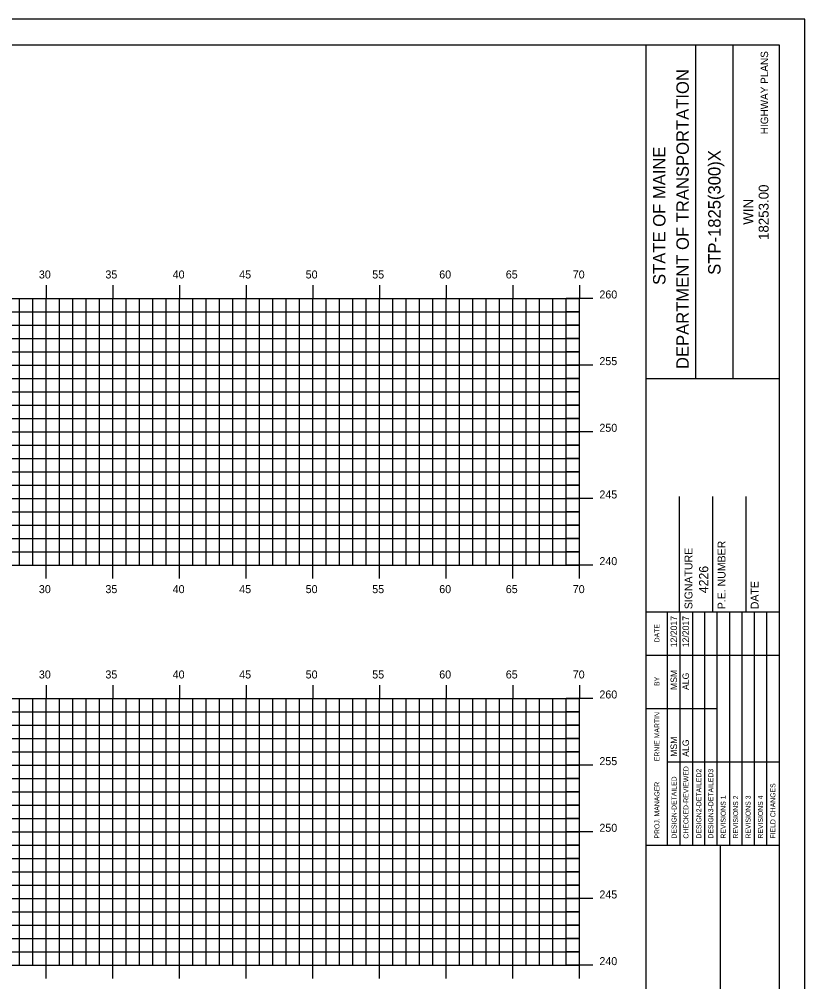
# Model space of a CAD drawing. Extents: x 859575 to 859745, y 366268 to 366378.
# Drawn here: x 859685.8 to 859744.7, y 366306 to 366378.2 of the extents above; entities that cross this region are included whole.
import ezdxf

# ---------------------------------------------------------------- set-up
doc = ezdxf.new("R2010")
doc.units = 0
for name, color, linetype in [('ANNOTATION', 7, 'Continuous'), ('BORDER', 7, 'Continuous'), ('H_V ANNOTATION', 7, 'Continuous'), ('HIGHWAY_TITLE', 7, 'Continuous'), ('MAJOR', 7, 'Continuous'), ('MINOR', 7, 'Continuous'), ('PLOT BOUNDARY', 7, 'Continuous')]:
    doc.layers.add(name, color=color, linetype=linetype)

msp = doc.modelspace()

# ---------------------------------------------------------------- linework, layer by layer
at = {"layer": 'BORDER'}
for p, q in [((859742.797, 366376.236), (859582.797, 366376.236)), ((859732.797, 366271.236), (859732.797, 366376.239)), ((859736.526, 366351.234), (859736.526, 366376.234)), ((859739.321, 366351.234), (859739.321, 366376.234)), ((859742.797, 366271.236), (859742.797, 366376.236)), ((859732.798, 366351.231), (859742.797, 366351.231)), ((859735.297, 366333.739), (859735.297, 366342.387)), ((859737.797, 366333.739), (859737.797, 366342.387)), ((859740.297, 366333.739), (859740.297, 366342.387)), ((859732.797, 366333.739), (859742.797, 366333.739)), ((859732.797, 366316.239), (859742.797, 366316.239)), ((859738.388, 366281.239), (859738.388, 366316.239))]:
    msp.add_line(p, q, dxfattribs=at)
for points in [[(859734.412, 366330.489), (859734.412, 366333.739)], [(859735.345, 366316.242), (859735.345, 366333.739)], [(859736.277, 366333.739), (859736.277, 366316.242)], [(859737.208, 366316.242), (859737.208, 366333.739)], [(859738.14, 366316.242), (859738.14, 366333.739)], [(859739.072, 366316.242), (859739.072, 366333.739)], [(859740.003, 366316.242), (859740.003, 366333.739)], [(859740.935, 366316.242), (859740.935, 366333.739)], [(859741.867, 366316.242), (859741.867, 366333.739)], [(859734.413, 366316.242), (859734.413, 366333.033)], [(859732.797, 366330.489), (859742.797, 366330.489)], [(859732.797, 366326.489), (859734.413, 366326.489)], [(859734.412, 366326.489), (859738.139, 366326.489)], [(859734.412, 366322.489), (859742.797, 366322.489)]]:
    msp.add_lwpolyline(points, dxfattribs=at)
at = {"layer": 'MAJOR'}
for p, q in [((859687.797, 366358.238), (859687.797, 366357.236)), ((859692.797, 366358.238), (859692.797, 366357.236)), ((859697.797, 366358.238), (859697.797, 366357.236)), ((859702.797, 366358.238), (859702.797, 366357.236)), ((859707.797, 366358.238), (859707.797, 366357.236)), ((859712.797, 366358.238), (859712.797, 366357.236)), ((859717.797, 366358.238), (859717.797, 366357.236)), ((859722.797, 366358.238), (859722.797, 366357.236)), ((859727.797, 366358.238), (859727.797, 366357.236)), ((859587.797, 366357.236), (859727.797, 366357.236)), ((859587.797, 366357.236), (859727.797, 366357.236)), ((859587.797, 366357.236), (859727.797, 366357.236)), ((859687.797, 366337.236), (859687.797, 366357.236)), ((859687.797, 366337.236), (859687.797, 366357.236)), ((859692.797, 366337.236), (859692.797, 366357.236)), ((859692.797, 366337.236), (859692.797, 366357.236)), ((859697.797, 366337.236), (859697.797, 366357.236)), ((859697.797, 366337.236), (859697.797, 366357.236)), ((859702.797, 366337.236), (859702.797, 366357.236)), ((859702.797, 366337.236), (859702.797, 366357.236)), ((859707.797, 366337.236), (859707.797, 366357.236)), ((859707.797, 366337.236), (859707.797, 366357.236)), ((859712.797, 366337.236), (859712.797, 366357.236)), ((859712.797, 366337.236), (859712.797, 366357.236)), ((859717.797, 366337.236), (859717.797, 366357.236)), ((859717.797, 366337.236), (859717.797, 366357.236)), ((859722.797, 366337.236), (859722.797, 366357.236)), ((859722.797, 366337.236), (859722.797, 366357.236)), ((859728.799, 366357.236), (859726.795, 366357.236)), ((859727.797, 366337.236), (859727.797, 366357.236)), ((859727.797, 366337.236), (859727.797, 366357.236)), ((859727.797, 366337.236), (859727.797, 366357.236)), ((859587.797, 366352.236), (859727.797, 366352.236)), ((859587.797, 366352.236), (859727.797, 366352.236)), ((859728.799, 366352.236), (859726.795, 366352.236)), ((859587.797, 366347.236), (859727.797, 366347.236)), ((859587.797, 366347.236), (859727.797, 366347.236)), ((859728.799, 366347.236), (859726.795, 366347.236)), ((859587.797, 366342.236), (859727.797, 366342.236)), ((859587.797, 366342.236), (859727.797, 366342.236)), ((859728.799, 366342.236), (859726.795, 366342.236)), ((859587.797, 366337.236), (859727.797, 366337.236)), ((859587.797, 366337.236), (859727.797, 366337.236)), ((859587.797, 366337.236), (859727.797, 366337.236)), ((859687.797, 366336.234), (859687.797, 366337.236)), ((859692.797, 366336.234), (859692.797, 366337.236)), ((859697.797, 366336.234), (859697.797, 366337.236)), ((859702.797, 366336.234), (859702.797, 366337.236)), ((859707.797, 366336.234), (859707.797, 366337.236)), ((859712.797, 366336.234), (859712.797, 366337.236)), ((859717.797, 366336.234), (859717.797, 366337.236)), ((859722.797, 366336.234), (859722.797, 366337.236)), ((859728.799, 366337.236), (859726.795, 366337.236)), ((859727.797, 366336.234), (859727.797, 366337.236)), ((859687.797, 366328.238), (859687.797, 366327.236)), ((859692.797, 366328.238), (859692.797, 366327.236)), ((859697.797, 366328.238), (859697.797, 366327.236)), ((859702.797, 366328.238), (859702.797, 366327.236)), ((859707.797, 366328.238), (859707.797, 366327.236)), ((859712.797, 366328.238), (859712.797, 366327.236)), ((859717.797, 366328.238), (859717.797, 366327.236)), ((859722.797, 366328.238), (859722.797, 366327.236)), ((859727.797, 366328.238), (859727.797, 366327.236)), ((859587.797, 366327.236), (859727.797, 366327.236)), ((859587.797, 366327.236), (859727.797, 366327.236)), ((859687.797, 366307.236), (859687.797, 366327.236)), ((859692.797, 366307.236), (859692.797, 366327.236)), ((859697.797, 366307.236), (859697.797, 366327.236)), ((859702.797, 366307.236), (859702.797, 366327.236)), ((859707.797, 366307.236), (859707.797, 366327.236)), ((859712.797, 366307.236), (859712.797, 366327.236)), ((859717.797, 366307.236), (859717.797, 366327.236)), ((859722.797, 366307.236), (859722.797, 366327.236)), ((859728.799, 366327.236), (859726.795, 366327.236)), ((859727.797, 366307.236), (859727.797, 366327.236)), ((859727.797, 366307.236), (859727.797, 366327.236)), ((859587.797, 366322.236), (859727.797, 366322.236)), ((859728.799, 366322.236), (859726.795, 366322.236)), ((859587.797, 366317.236), (859727.797, 366317.236)), ((859728.799, 366317.236), (859726.795, 366317.236)), ((859587.797, 366312.236), (859727.797, 366312.236)), ((859728.799, 366312.236), (859726.795, 366312.236)), ((859587.797, 366307.236), (859727.797, 366307.236)), ((859587.797, 366307.236), (859727.797, 366307.236)), ((859687.797, 366306.234), (859687.797, 366307.236)), ((859692.797, 366306.234), (859692.797, 366307.236)), ((859697.797, 366306.234), (859697.797, 366307.236)), ((859702.797, 366306.234), (859702.797, 366307.236)), ((859707.797, 366306.234), (859707.797, 366307.236)), ((859712.797, 366306.234), (859712.797, 366307.236)), ((859717.797, 366306.234), (859717.797, 366307.236)), ((859722.797, 366306.234), (859722.797, 366307.236)), ((859728.799, 366307.236), (859726.795, 366307.236)), ((859727.797, 366306.234), (859727.797, 366307.236))]:
    msp.add_line(p, q, dxfattribs=at)
at = {"layer": 'MINOR'}
for p, q in [((859685.797, 366337.236), (859685.797, 366357.236)), ((859685.797, 366337.236), (859685.797, 366357.236)), ((859686.797, 366337.236), (859686.797, 366357.236)), ((859686.797, 366337.236), (859686.797, 366357.236)), ((859688.797, 366337.236), (859688.797, 366357.236)), ((859688.797, 366337.236), (859688.797, 366357.236)), ((859689.797, 366337.236), (859689.797, 366357.236)), ((859689.797, 366337.236), (859689.797, 366357.236)), ((859690.797, 366337.236), (859690.797, 366357.236)), ((859690.797, 366337.236), (859690.797, 366357.236)), ((859691.797, 366337.236), (859691.797, 366357.236)), ((859691.797, 366337.236), (859691.797, 366357.236)), ((859693.797, 366337.236), (859693.797, 366357.236)), ((859693.797, 366337.236), (859693.797, 366357.236)), ((859694.797, 366337.236), (859694.797, 366357.236)), ((859694.797, 366337.236), (859694.797, 366357.236)), ((859695.797, 366337.236), (859695.797, 366357.236)), ((859695.797, 366337.236), (859695.797, 366357.236)), ((859696.797, 366337.236), (859696.797, 366357.236)), ((859696.797, 366337.236), (859696.797, 366357.236)), ((859698.797, 366337.236), (859698.797, 366357.236)), ((859698.797, 366337.236), (859698.797, 366357.236)), ((859699.797, 366337.236), (859699.797, 366357.236)), ((859699.797, 366337.236), (859699.797, 366357.236)), ((859700.797, 366337.236), (859700.797, 366357.236)), ((859700.797, 366337.236), (859700.797, 366357.236)), ((859701.797, 366337.236), (859701.797, 366357.236)), ((859701.797, 366337.236), (859701.797, 366357.236)), ((859703.797, 366337.236), (859703.797, 366357.236)), ((859703.797, 366337.236), (859703.797, 366357.236)), ((859704.797, 366337.236), (859704.797, 366357.236)), ((859704.797, 366337.236), (859704.797, 366357.236)), ((859705.797, 366337.236), (859705.797, 366357.236)), ((859705.797, 366337.236), (859705.797, 366357.236)), ((859706.797, 366337.236), (859706.797, 366357.236)), ((859706.797, 366337.236), (859706.797, 366357.236)), ((859708.797, 366337.236), (859708.797, 366357.236)), ((859708.797, 366337.236), (859708.797, 366357.236)), ((859709.797, 366337.236), (859709.797, 366357.236)), ((859709.797, 366337.236), (859709.797, 366357.236)), ((859710.797, 366337.236), (859710.797, 366357.236)), ((859710.797, 366337.236), (859710.797, 366357.236)), ((859711.797, 366337.236), (859711.797, 366357.236)), ((859711.797, 366337.236), (859711.797, 366357.236)), ((859713.797, 366337.236), (859713.797, 366357.236)), ((859713.797, 366337.236), (859713.797, 366357.236)), ((859714.797, 366337.236), (859714.797, 366357.236)), ((859714.797, 366337.236), (859714.797, 366357.236)), ((859715.797, 366337.236), (859715.797, 366357.236)), ((859715.797, 366337.236), (859715.797, 366357.236)), ((859716.797, 366337.236), (859716.797, 366357.236)), ((859716.797, 366337.236), (859716.797, 366357.236)), ((859718.797, 366337.236), (859718.797, 366357.236)), ((859718.797, 366337.236), (859718.797, 366357.236)), ((859719.797, 366337.236), (859719.797, 366357.236)), ((859719.797, 366337.236), (859719.797, 366357.236)), ((859720.797, 366337.236), (859720.797, 366357.236)), ((859720.797, 366337.236), (859720.797, 366357.236)), ((859721.797, 366337.236), (859721.797, 366357.236)), ((859721.797, 366337.236), (859721.797, 366357.236)), ((859723.797, 366337.236), (859723.797, 366357.236)), ((859723.797, 366337.236), (859723.797, 366357.236)), ((859724.797, 366337.236), (859724.797, 366357.236)), ((859724.797, 366337.236), (859724.797, 366357.236)), ((859725.797, 366337.236), (859725.797, 366357.236)), ((859725.797, 366337.236), (859725.797, 366357.236)), ((859726.797, 366337.236), (859726.797, 366357.236)), ((859726.797, 366337.236), (859726.797, 366357.236)), ((859587.797, 366356.236), (859727.797, 366356.236)), ((859587.797, 366356.236), (859727.797, 366356.236)), ((859727.797, 366356.236), (859726.795, 366356.236)), ((859587.797, 366355.236), (859727.797, 366355.236)), ((859587.797, 366355.236), (859727.797, 366355.236)), ((859727.797, 366355.236), (859726.795, 366355.236)), ((859587.797, 366354.236), (859727.797, 366354.236)), ((859587.797, 366354.236), (859727.797, 366354.236)), ((859727.797, 366354.236), (859726.795, 366354.236)), ((859587.797, 366353.236), (859727.797, 366353.236)), ((859587.797, 366353.236), (859727.797, 366353.236)), ((859727.797, 366353.236), (859726.795, 366353.236)), ((859587.797, 366351.236), (859727.797, 366351.236)), ((859587.797, 366351.236), (859727.797, 366351.236)), ((859727.797, 366351.236), (859726.795, 366351.236)), ((859587.797, 366350.236), (859727.797, 366350.236)), ((859587.797, 366350.236), (859727.797, 366350.236)), ((859727.797, 366350.236), (859726.795, 366350.236)), ((859587.797, 366349.236), (859727.797, 366349.236)), ((859587.797, 366349.236), (859727.797, 366349.236)), ((859727.797, 366349.236), (859726.795, 366349.236)), ((859587.797, 366348.236), (859727.797, 366348.236)), ((859587.797, 366348.236), (859727.797, 366348.236)), ((859727.797, 366348.236), (859726.795, 366348.236)), ((859587.797, 366346.236), (859727.797, 366346.236)), ((859587.797, 366346.236), (859727.797, 366346.236)), ((859727.797, 366346.236), (859726.795, 366346.236)), ((859587.797, 366345.236), (859727.797, 366345.236)), ((859587.797, 366345.236), (859727.797, 366345.236)), ((859727.797, 366345.236), (859726.795, 366345.236)), ((859587.797, 366344.236), (859727.797, 366344.236)), ((859587.797, 366344.236), (859727.797, 366344.236)), ((859727.797, 366344.236), (859726.795, 366344.236)), ((859587.797, 366343.236), (859727.797, 366343.236)), ((859587.797, 366343.236), (859727.797, 366343.236)), ((859727.797, 366343.236), (859726.795, 366343.236)), ((859587.797, 366341.236), (859727.797, 366341.236)), ((859587.797, 366341.236), (859727.797, 366341.236)), ((859727.797, 366341.236), (859726.795, 366341.236)), ((859587.797, 366340.236), (859727.797, 366340.236)), ((859587.797, 366340.236), (859727.797, 366340.236)), ((859727.797, 366340.236), (859726.795, 366340.236)), ((859587.797, 366339.236), (859727.797, 366339.236)), ((859587.797, 366339.236), (859727.797, 366339.236)), ((859727.797, 366339.236), (859726.795, 366339.236)), ((859587.797, 366338.236), (859727.797, 366338.236)), ((859587.797, 366338.236), (859727.797, 366338.236)), ((859727.797, 366338.236), (859726.795, 366338.236)), ((859685.797, 366307.236), (859685.797, 366327.236)), ((859686.797, 366307.236), (859686.797, 366327.236)), ((859688.797, 366307.236), (859688.797, 366327.236)), ((859689.797, 366307.236), (859689.797, 366327.236)), ((859690.797, 366307.236), (859690.797, 366327.236)), ((859691.797, 366307.236), (859691.797, 366327.236)), ((859693.797, 366307.236), (859693.797, 366327.236)), ((859694.797, 366307.236), (859694.797, 366327.236)), ((859695.797, 366307.236), (859695.797, 366327.236)), ((859696.797, 366307.236), (859696.797, 366327.236)), ((859698.797, 366307.236), (859698.797, 366327.236)), ((859699.797, 366307.236), (859699.797, 366327.236)), ((859700.797, 366307.236), (859700.797, 366327.236)), ((859701.797, 366307.236), (859701.797, 366327.236)), ((859703.797, 366307.236), (859703.797, 366327.236)), ((859704.797, 366307.236), (859704.797, 366327.236)), ((859705.797, 366307.236), (859705.797, 366327.236)), ((859706.797, 366307.236), (859706.797, 366327.236)), ((859708.797, 366307.236), (859708.797, 366327.236)), ((859709.797, 366307.236), (859709.797, 366327.236)), ((859710.797, 366307.236), (859710.797, 366327.236)), ((859711.797, 366307.236), (859711.797, 366327.236)), ((859713.797, 366307.236), (859713.797, 366327.236)), ((859714.797, 366307.236), (859714.797, 366327.236)), ((859715.797, 366307.236), (859715.797, 366327.236)), ((859716.797, 366307.236), (859716.797, 366327.236)), ((859718.797, 366307.236), (859718.797, 366327.236)), ((859719.797, 366307.236), (859719.797, 366327.236)), ((859720.797, 366307.236), (859720.797, 366327.236)), ((859721.797, 366307.236), (859721.797, 366327.236)), ((859723.797, 366307.236), (859723.797, 366327.236)), ((859724.797, 366307.236), (859724.797, 366327.236)), ((859725.797, 366307.236), (859725.797, 366327.236)), ((859726.797, 366307.236), (859726.797, 366327.236)), ((859587.797, 366326.236), (859727.797, 366326.236)), ((859727.797, 366326.236), (859726.795, 366326.236)), ((859587.797, 366325.236), (859727.797, 366325.236)), ((859727.797, 366325.236), (859726.795, 366325.236)), ((859587.797, 366324.236), (859727.797, 366324.236)), ((859727.797, 366324.236), (859726.795, 366324.236)), ((859587.797, 366323.236), (859727.797, 366323.236)), ((859727.797, 366323.236), (859726.795, 366323.236)), ((859587.797, 366321.236), (859727.797, 366321.236)), ((859727.797, 366321.236), (859726.795, 366321.236)), ((859587.797, 366320.236), (859727.797, 366320.236)), ((859727.797, 366320.236), (859726.795, 366320.236)), ((859587.797, 366319.236), (859727.797, 366319.236)), ((859727.797, 366319.236), (859726.795, 366319.236)), ((859587.797, 366318.236), (859727.797, 366318.236)), ((859727.797, 366318.236), (859726.795, 366318.236)), ((859587.797, 366316.236), (859727.797, 366316.236)), ((859727.797, 366316.236), (859726.795, 366316.236)), ((859587.797, 366315.236), (859727.797, 366315.236)), ((859727.797, 366315.236), (859726.795, 366315.236)), ((859587.797, 366314.236), (859727.797, 366314.236)), ((859727.797, 366314.236), (859726.795, 366314.236)), ((859587.797, 366313.236), (859727.797, 366313.236)), ((859727.797, 366313.236), (859726.795, 366313.236)), ((859587.797, 366311.236), (859727.797, 366311.236)), ((859727.797, 366311.236), (859726.795, 366311.236)), ((859587.797, 366310.236), (859727.797, 366310.236)), ((859727.797, 366310.236), (859726.795, 366310.236)), ((859587.797, 366309.236), (859727.797, 366309.236)), ((859727.797, 366309.236), (859726.795, 366309.236)), ((859587.797, 366308.236), (859727.797, 366308.236)), ((859727.797, 366308.236), (859726.795, 366308.236))]:
    msp.add_line(p, q, dxfattribs=at)
at = {"layer": 'PLOT BOUNDARY'}
msp.add_lwpolyline([(859574.704, 366268.177), (859744.704, 366268.177), (859744.704, 366378.177), (859574.704, 366378.177)], close=True, dxfattribs=at)

# ---------------------------------------------------------------- texts
at = {"layer": 'ANNOTATION'}
msp.add_text('4226', height=0.69, rotation=90, dxfattribs=at).set_placement((859737.462, 366335.13))
at = {"layer": 'BORDER'}
for s, height, p in [('DEPARTMENT OF TRANSPORTATION', 0.93176, (859736.004, 366351.942)), ('STATE OF MAINE', 0.93176, (859734.253, 366358.248)), ('STP-1825(300)X', 0.93176, (859738.389, 366359.008)), ('18253.00', 0.7453, (859741.993, 366361.623)), ('WIN', 0.7453, (859740.834, 366362.766)), ('P.E. NUMBER', 0.59055, (859738.758, 366333.932)), ('SIGNATURE', 0.5906, (859736.278, 366333.932)), ('DATE', 0.5906, (859741.238, 366333.932)), ('12/2017', 0.4845, (859735.12, 366331.081)), ('12/2017', 0.4845, (859736.015, 366331.081)), ('DATE', 0.3714, (859733.802, 366331.445)), ('MSM', 0.4845, (859735.12, 366327.872)), ('BY', 0.3714, (859733.802, 366328.174)), ('ALG', 0.4845, (859736.015, 366327.872)), ('ERNIE MARTIN', 0.37275, (859733.802, 366322.531)), ('MSM', 0.4845, (859735.12, 366322.863)), ('ALG', 0.4845, (859736.015, 366322.863)), ('CHECKED-REVIEWED', 0.37275, (859735.978, 366316.727)), ('DESIGN2-DETAILED2', 0.37275, (859736.947, 366316.727)), ('DESIGN3-DETAILED3', 0.37275, (859737.842, 366316.727)), ('PROJ. MANAGER', 0.37275, (859733.802, 366316.727)), ('DESIGN-DETAILED', 0.37275, (859735.084, 366316.727)), ('FIELD CHANGES', 0.37275, (859742.5, 366316.727)), ('REVISIONS 1', 0.37275, (859738.773, 366316.727)), ('REVISIONS 2', 0.37275, (859739.705, 366316.727)), ('REVISIONS 3', 0.37275, (859740.637, 366316.727)), ('REVISIONS 4', 0.37275, (859741.568, 366316.727))]:
    msp.add_text(s, height=height, rotation=90, dxfattribs=at).set_placement(p)
at = {"layer": 'H_V ANNOTATION'}
for s, p in [('30', (859687.246, 366358.736)), ('35', (859692.238, 366358.736)), ('40', (859697.283, 366358.736)), ('45', (859702.275, 366358.736)), ('50', (859707.262, 366358.736)), ('55', (859712.254, 366358.736)), ('60', (859717.283, 366358.736)), ('65', (859722.275, 366358.736)), ('70', (859727.299, 366358.736)), ('260', (859729.297, 366357.236)), ('255', (859729.297, 366352.236)), ('250', (859729.297, 366347.236)), ('245', (859729.297, 366342.236)), ('240', (859729.297, 366337.236)), ('30', (859687.246, 366335.136)), ('35', (859692.238, 366335.136)), ('40', (859697.283, 366335.136)), ('45', (859702.275, 366335.136)), ('50', (859707.262, 366335.136)), ('55', (859712.254, 366335.136)), ('60', (859717.283, 366335.136)), ('65', (859722.275, 366335.136)), ('70', (859727.299, 366335.136)), ('30', (859687.246, 366328.736)), ('35', (859692.238, 366328.736)), ('40', (859697.283, 366328.736)), ('45', (859702.275, 366328.736)), ('50', (859707.262, 366328.736)), ('55', (859712.254, 366328.736)), ('60', (859717.283, 366328.736)), ('65', (859722.275, 366328.736)), ('70', (859727.299, 366328.736)), ('260', (859729.297, 366327.236)), ('255', (859729.297, 366322.236)), ('250', (859729.297, 366317.236)), ('245', (859729.297, 366312.236)), ('240', (859729.297, 366307.236))]:
    msp.add_text(s, height=0.6, dxfattribs=at).set_placement(p)
at = {"layer": 'HIGHWAY_TITLE'}
msp.add_text('HIGHWAY PLANS', height=0.55901, rotation=90, dxfattribs=at).set_placement((859741.956, 366369.552))

doc.saveas('drawing.dxf')
